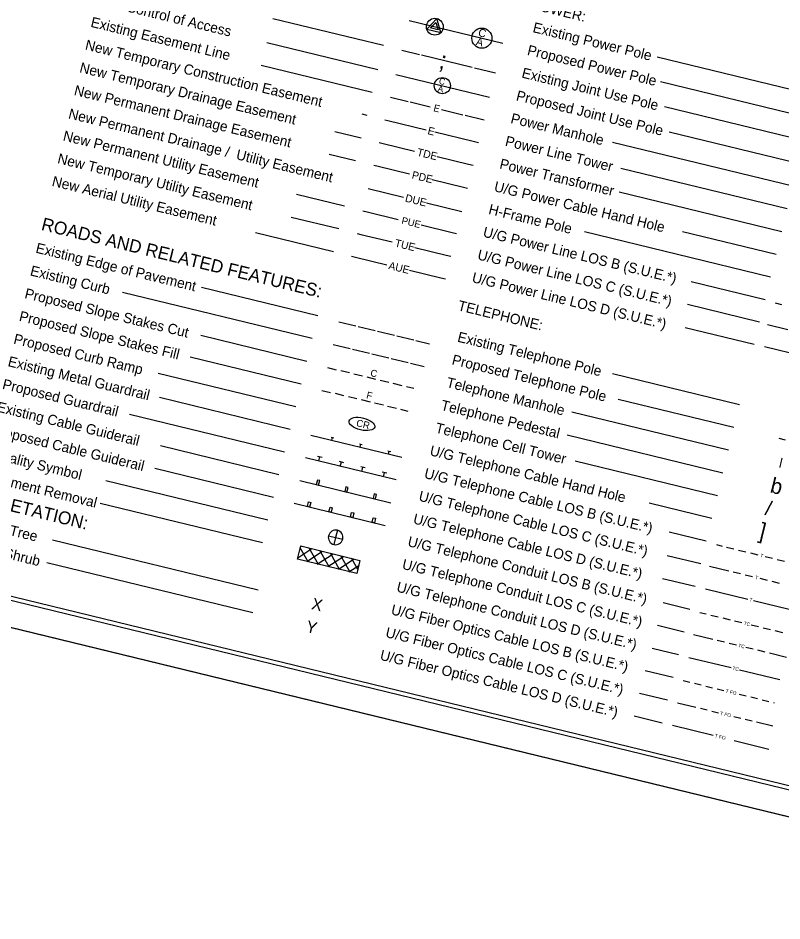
# Model space of a CAD drawing. Extents: x 1532568 to 1534465, y 472683 to 474150.
# Drawn here: x 1533179 to 1533832, y 472683 to 473455 of the extents above; entities that cross this region are included whole.
import ezdxf

# ---------------------------------------------------------------- set-up
doc = ezdxf.new("R2010")
doc.units = 0
for name, color, linetype in [('Prop Easement Permanent Drainage Utility', 7, 'Continuous'), ('Prop WCC CELL', 7, 'Continuous'), ('Sheet Cutting Line CELL', 7, 'Continuous'), ('Sheet Plot Border Inside CELL', 7, 'Continuous'), ('Sheet Plot Border Outside CELL', 7, 'Continuous'), ('Sheet Symbology CELL', 7, 'Continuous')]:
    doc.layers.add(name, color=color, linetype=linetype)

msp = doc.modelspace()

# ---------------------------------------------------------------- linework, layer by layer
at = {"layer": 'Prop Easement Permanent Drainage Utility'}
for p, q in [((1533478.48, 473309.25), (1533508.89, 473301.85)), ((1533528.32, 473297.12), (1533558.64, 473289.74))]:
    msp.add_line(p, q, dxfattribs=at)
at = {"layer": 'Prop WCC CELL'}
msp.add_ellipse((1533473.2, 473108.01), major_axis=(10.9, -2.65), ratio=0.462467, dxfattribs=at)
at = {"layer": 'Sheet Cutting Line CELL'}
msp.add_line((1532568.24, 473081.26), (1534204.47, 472683), dxfattribs=at)
at = {"layer": 'Sheet Plot Border Inside CELL'}
msp.add_lwpolyline([(1532586.18, 473100), (1534205.41, 472705.88), (1534454.94, 473731.04), (1532835.71, 474125.17)], close=True, dxfattribs=at)
at = {"layer": 'Sheet Plot Border Outside CELL'}
msp.add_lwpolyline([(1532568.24, 473081.26), (1534204.47, 472683), (1534464.62, 473751.79), (1532828.39, 474150.06)], close=True, dxfattribs=at)
at = {"layer": 'Sheet Symbology CELL'}
for p, q in [((1533491.74, 473431.51), (1533396.96, 473454.58)), ((1533513.48, 473453.06), (1533593.64, 473433.55)), ((1533535.54, 473447.69), (1533535.54, 473447.69)), ((1533486.69, 473410.77), (1533391.91, 473433.84)), ((1533507.31, 473427.72), (1533522.34, 473424.06)), ((1533524.28, 473423.59), (1533567.43, 473413.09)), ((1533860.48, 473389), (1533725.71, 473421.8)), ((1533481.96, 473391.33), (1533387.18, 473414.4)), ((1533502.27, 473406.97), (1533582.42, 473387.46)), ((1533569.38, 473412.61), (1533587.47, 473408.21)), ((1533855.75, 473369.57), (1533728.55, 473400.53)), ((1533497.54, 473387.54), (1533512.61, 473383.87)), ((1533514.55, 473383.4), (1533531.55, 473379.26)), ((1533541.27, 473376.9), (1533559.49, 473372.46)), ((1533851.02, 473350.14), (1533731.98, 473379.11)), ((1533477.6, 473371.81), (1533473.55, 473372.8)), ((1533492.81, 473368.11), (1533495.34, 473367.49)), ((1533495.34, 473367.49), (1533528.14, 473359.51)), ((1533561.43, 473371.99), (1533577.69, 473368.03)), ((1533472.5, 473352.47), (1533450.01, 473357.94)), ((1533535.42, 473357.74), (1533568.22, 473349.75)), ((1533846.29, 473330.7), (1533736, 473357.55)), ((1533488.08, 473348.68), (1533491.33, 473347.88)), ((1533491.33, 473347.88), (1533518.05, 473341.38)), ((1533568.22, 473349.75), (1533572.96, 473348.6)), ((1533841.56, 473311.27), (1533687.56, 473348.76)), ((1533467.77, 473333.04), (1533445.28, 473338.51)), ((1533537.48, 473336.65), (1533564.2, 473330.15)), ((1533483.35, 473329.24), (1533487.04, 473328.35)), ((1533487.04, 473328.35), (1533513.76, 473321.84)), ((1533564.2, 473330.15), (1533568.23, 473329.17)), ((1533836.83, 473291.84), (1533694.48, 473326.49)), ((1533533.19, 473317.11), (1533559.91, 473310.61)), ((1533559.91, 473310.61), (1533563.5, 473309.73)), ((1533832.1, 473272.41), (1533693.25, 473306.2)), ((1533458.31, 473294.16), (1533417.37, 473304.13)), ((1533473.88, 473290.37), (1533477.61, 473289.46)), ((1533477.61, 473289.46), (1533504.33, 473282.96)), ((1533453.58, 473274.73), (1533412.64, 473284.69)), ((1533523.76, 473278.23), (1533550.48, 473271.73)), ((1533448.85, 473255.3), (1533382.33, 473271.49)), ((1533469.15, 473270.94), (1533472.41, 473270.15)), ((1533472.41, 473270.15), (1533499.13, 473263.64)), ((1533550.48, 473271.73), (1533554.04, 473270.86)), ((1533822.64, 473233.54), (1533663.39, 473272.3)), ((1533827.37, 473252.97), (1533747.38, 473272.44)), ((1533518.56, 473258.91), (1533545.28, 473252.41)), ((1533464.42, 473251.51), (1533467.68, 473250.71)), ((1533467.68, 473250.71), (1533494.4, 473244.21)), ((1533545.28, 473252.41), (1533549.31, 473251.43)), ((1533513.83, 473239.48), (1533540.55, 473232.98)), ((1533540.55, 473232.98), (1533544.58, 473231.99)), ((1533817.91, 473214.11), (1533754.83, 473229.46)), ((1533430.76, 473180.98), (1533268.35, 473220.51)), ((1533435.49, 473200.41), (1533336.04, 473224.62)), ((1533813.27, 473195.05), (1533751.69, 473210.04)), ((1533826.55, 473211.5), (1533831.89, 473210.2)), ((1533453.36, 473195.47), (1533467.93, 473191.92)), ((1533469.88, 473191.45), (1533484.45, 473187.9)), ((1533808.63, 473175.99), (1533749.66, 473190.34)), ((1533819.97, 473193.02), (1533837.48, 473188.76)), ((1533426.03, 473161.55), (1533335.49, 473183.59)), ((1533486.39, 473187.43), (1533500.97, 473183.88)), ((1533502.91, 473183.41), (1533517.49, 473179.86)), ((1533448.63, 473176.04), (1533463.2, 473172.49)), ((1533519.43, 473179.39), (1533531.09, 473176.55)), ((1533817.45, 473174.12), (1533854.46, 473165.12)), ((1533465.15, 473172.02), (1533479.72, 473168.47)), ((1533481.66, 473168), (1533496.24, 473164.45)), ((1533421.3, 473142.11), (1533326.33, 473165.23)), ((1533498.18, 473163.98), (1533512.76, 473160.43)), ((1533514.7, 473159.96), (1533526.36, 473157.12)), ((1533416.57, 473122.68), (1533299.07, 473151.28)), ((1533443.79, 473156.14), (1533451.17, 473154.35)), ((1533462.54, 473151.58), (1533455.2, 473153.37)), ((1533473.71, 473148.86), (1533466.33, 473150.66)), ((1533796.05, 473124.32), (1533687.34, 473150.78)), ((1533485.13, 473146.08), (1533477.55, 473147.93)), ((1533496.25, 473143.37), (1533488.72, 473145.21)), ((1533507.48, 473140.64), (1533499.85, 473142.5)), ((1533439.06, 473136.71), (1533446.44, 473134.91)), ((1533517.48, 473138.21), (1533511.26, 473139.72)), ((1533411.72, 473103.4), (1533300.14, 473130.56)), ((1533457.81, 473132.15), (1533450.47, 473133.93)), ((1533468.98, 473129.43), (1533461.6, 473131.23)), ((1533480.4, 473126.65), (1533472.82, 473128.49)), ((1533791.32, 473104.88), (1533692.16, 473129.02)), ((1533491.52, 473123.94), (1533483.99, 473125.77)), ((1533502.75, 473121.21), (1533495.12, 473123.07)), ((1533512.75, 473118.77), (1533506.53, 473120.29)), ((1533406.99, 473083.97), (1533274.61, 473116.19)), ((1533786.59, 473085.45), (1533652.64, 473118.06)), ((1533429.58, 473098.46), (1533507.31, 473079.54)), ((1533446.83, 473096.84), (1533449.26, 473096.25)), ((1533447.45, 473094.11), (1533448.04, 473096.54)), ((1533781.86, 473066.02), (1533648.59, 473098.46)), ((1533402.26, 473064.54), (1533300.91, 473089.2)), ((1533471.12, 473090.93), (1533473.55, 473090.33)), ((1533471.74, 473088.2), (1533472.33, 473090.63)), ((1533835.34, 473094.16), (1533829.87, 473095.49)), ((1533495.41, 473085.01), (1533497.84, 473084.42)), ((1533496.03, 473082.29), (1533496.62, 473084.72)), ((1533502.58, 473060.11), (1533424.85, 473079.03)), ((1533435.24, 473080.57), (1533439.12, 473079.62)), ((1533436.25, 473076.26), (1533437.18, 473080.09)), ((1533453.7, 473076.07), (1533457.58, 473075.13)), ((1533454.71, 473071.76), (1533455.64, 473075.6)), ((1533777.13, 473046.59), (1533655.46, 473076.2)), ((1533397.53, 473045.11), (1533296.18, 473069.77)), ((1533472.16, 473071.58), (1533476.05, 473070.63)), ((1533473.17, 473067.27), (1533474.1, 473071.11)), ((1533490.62, 473067.09), (1533494.51, 473066.14)), ((1533491.63, 473062.78), (1533492.56, 473066.61)), ((1533392.8, 473025.67), (1533254.22, 473059.4)), ((1533420.12, 473059.6), (1533497.85, 473040.68)), ((1533388.07, 473006.24), (1533249.49, 473039.97)), ((1533415.39, 473040.16), (1533493.12, 473021.24)), ((1533772.4, 473027.15), (1533718.93, 473040.17)), ((1533444.64, 473012.45), (1533450.72, 473010.97)), ((1533452.19, 473017.04), (1533450.72, 473010.97)), ((1533767.67, 473007.72), (1533735.82, 473015.47)), ((1533384.55, 472965.86), (1533208.57, 473008.69)), ((1533418.11, 472992.33), (1533420.87, 473003.7)), ((1533420.73, 473003.11), (1533421.41, 473003.57)), ((1533420.87, 473003.7), (1533471.5, 472991.37)), ((1533450.72, 473010.97), (1533449.24, 473004.9)), ((1533450.72, 473010.97), (1533456.79, 473009.49)), ((1533776.24, 473004.81), (1533781.12, 473003.63)), ((1533418.38, 472993.45), (1533430.45, 473001.37)), ((1533427.1, 472990.14), (1533420.45, 473001.95)), ((1533426.03, 472990.4), (1533439.48, 472999.17)), ((1533436.13, 472987.94), (1533428.21, 473001.91)), ((1533435.01, 472988.21), (1533448.52, 472996.97)), ((1533445.12, 472985.75), (1533437.25, 472999.71)), ((1533454.15, 472983.55), (1533446.23, 472997.52)), ((1533785.01, 473002.68), (1533791.33, 473001.14)), ((1533795.21, 473000.2), (1533801.53, 472998.66)), ((1533805.41, 472997.71), (1533811.73, 472996.18)), ((1533379.82, 472946.42), (1533203.84, 472989.26)), ((1533468.73, 472980.01), (1533418.11, 472992.33)), ((1533444.05, 472986.01), (1533457.51, 472994.78)), ((1533453.09, 472983.81), (1533466.49, 472992.59)), ((1533463.19, 472981.35), (1533455.22, 472995.34)), ((1533469.62, 472983.65), (1533464.26, 472993.14)), ((1533471.5, 472991.37), (1533468.73, 472980.01)), ((1533762.94, 472988.29), (1533734.16, 472995.3)), ((1533817.95, 472994.66), (1533824.26, 472993.13)), ((1533828.15, 472992.18), (1533834.47, 472990.64)), ((1533462.07, 472981.63), (1533470.46, 472987.1)), ((1533770.48, 472986.45), (1533786.79, 472982.49)), ((1533790.67, 472981.54), (1533796.99, 472980)), ((1533758.21, 472968.86), (1533730.18, 472975.68)), ((1533800.87, 472979.06), (1533807.19, 472977.52)), ((1533813.41, 472976.01), (1533819.72, 472974.47)), ((1533823.61, 472973.52), (1533829.93, 472971.99)), ((1533767.05, 472967.07), (1533803.13, 472958.29)), ((1533753.48, 472949.42), (1533730.69, 472954.97)), ((1533807.98, 472957.1), (1533849.16, 472947.08)), ((1533762.14, 472946.88), (1533767.57, 472945.56)), ((1533771.45, 472944.61), (1533777.77, 472943.07)), ((1533781.66, 472942.13), (1533787.97, 472940.59)), ((1533748.75, 472929.99), (1533725.96, 472935.54)), ((1533791.86, 472939.64), (1533798.17, 472938.11)), ((1533805.95, 472936.21), (1533812.26, 472934.68)), ((1533756.59, 472928.08), (1533773.14, 472924.06)), ((1533816.15, 472933.73), (1533822.47, 472932.19)), ((1533826.35, 472931.25), (1533832.67, 472929.71)), ((1533777.03, 472923.11), (1533783.34, 472921.57)), ((1533787.23, 472920.63), (1533793.55, 472919.09)), ((1533744.02, 472910.56), (1533721.23, 472916.11)), ((1533801.32, 472917.2), (1533807.63, 472915.66)), ((1533811.52, 472914.71), (1533817.84, 472913.18)), ((1533821.72, 472912.23), (1533836.17, 472908.71)), ((1533752.77, 472908.38), (1533788.8, 472899.61)), ((1533739.29, 472891.13), (1533715.37, 472896.95)), ((1533796.09, 472897.84), (1533830.5, 472889.46)), ((1533747.95, 472888.57), (1533753.62, 472887.19)), ((1533757.51, 472886.24), (1533763.34, 472884.83)), ((1533767.22, 472883.88), (1533773.05, 472882.46)), ((1533776.94, 472881.51), (1533782.77, 472880.1)), ((1533734.56, 472871.69), (1533710.64, 472877.52)), ((1533795.89, 472876.9), (1533801.72, 472875.48)), ((1533805.6, 472874.54), (1533811.43, 472873.12)), ((1533743.14, 472869.6), (1533758.71, 472865.82)), ((1533762.6, 472864.87), (1533768.43, 472863.45)), ((1533815.32, 472872.17), (1533821.15, 472870.75)), ((1533825.03, 472869.81), (1533825.68, 472869.65)), ((1533729.83, 472852.26), (1533705.91, 472858.08)), ((1533772.31, 472862.51), (1533778.14, 472861.09)), ((1533791.26, 472857.89), (1533797.09, 472856.47)), ((1533738.67, 472850.45), (1533773.53, 472841.96)), ((1533800.97, 472855.53), (1533806.8, 472854.11)), ((1533810.69, 472853.16), (1533824.6, 472849.78)), ((1533791.41, 472837.22), (1533821.17, 472829.97))]:
    msp.add_line(p, q, dxfattribs=at)
for points in [[(1534442.19, 473731.52), (1532984.74, 474086.27), (1532736.66, 473067.05), (1534194.1, 472712.3)], [(1533528.61, 473445.67), (1533540.76, 473442.72), (1533537.24, 473454.69)], [(1533531.92, 473446.64), (1533536.43, 473451.35), (1533538.27, 473445.09)], [(1533434.19, 473056.17), (1533436.13, 473055.7), (1533437.08, 473059.59), (1533435.13, 473060.06)], [(1533458.48, 473050.26), (1533460.42, 473049.79), (1533461.37, 473053.67), (1533459.42, 473054.15)], [(1533482.77, 473044.35), (1533484.71, 473043.88), (1533485.66, 473047.76), (1533483.72, 473048.24)], [(1533427.48, 473041.34), (1533429.42, 473040.87), (1533428.47, 473036.98), (1533426.53, 473037.45)], [(1533445.94, 473036.85), (1533447.88, 473036.37), (1533446.94, 473032.49), (1533444.99, 473032.96)], [(1533464.4, 473032.35), (1533466.34, 473031.88), (1533465.4, 473027.99), (1533463.45, 473028.47)], [(1533482.86, 473027.86), (1533484.8, 473027.39), (1533483.86, 473023.5), (1533481.91, 473023.97)]]:
    msp.add_lwpolyline(points, close=True, dxfattribs=at)
for centre, radius in [((1533535.54, 473447.69), 7.2), ((1533575.76, 473437.9), 8.61), ((1533541.98, 473397.31), 6.89)]:
    msp.add_circle(centre, radius, dxfattribs=at)
for start, end in [(166.31436, 256.3189), (76.31436, 166.3189), (346.31436, 76.3189), (256.31436, 346.3189)]:
    msp.add_arc((1533450.72, 473010.97), 6.25, start, end, dxfattribs=at)

# ---------------------------------------------------------------- texts
at = {"layer": 'Prop Easement Permanent Drainage Utility'}
msp.add_text('DUE', height=6.55, rotation=346.31998, dxfattribs=at).set_placement((1533509.66, 473298.26))
at = {"layer": 'Prop WCC CELL'}
msp.add_text('CR', height=6, rotation=346.31998, dxfattribs=at).set_placement((1533467.92, 473106.25))
at = {"layer": 'Sheet Symbology CELL'}
for s, height, p in [('New Control of Access', 8.75, (1533245.43, 473467.16)), ('POWER:', 8.75, (1533617.32, 473463.07)), ('Existing Easement Line', 8.75, (1533240.7, 473447.73)), ('Existing Power Pole', 8.75, (1533618.7, 473443.18)), ('C', 6.75, (1533572.15, 473439.82)), ('New Temporary Construction Easement', 8.75, (1533235.97, 473428.3)), ('A', 6.75, (1533570.21, 473432.11)), ('Proposed Power Pole', 8.75, (1533613.97, 473423.75)), (';', 15, (1533538.33, 473412.45)), ('New Temporary Drainage Easement', 8.75, (1533231.24, 473408.86)), ('Existing Joint Use Pole', 8.75, (1533609.24, 473404.33)), ('New Permanent Drainage Easement', 8.75, (1533226.51, 473389.43)), ('A', 5.4, (1533537.6, 473392.53)), ('C', 5.4, (1533538.61, 473398.96)), ('Proposed Joint Use Pole', 8.75, (1533604.52, 473384.88)), ('New Permanent Drainage /  Utility Easement', 8.75, (1533221.65, 473369.43)), ('E', 6, (1533533.95, 473375.59)), ('Power Manhole', 8.75, (1533599.79, 473365.45)), ('New Permanent Utility Easement', 8.75, (1533217.05, 473350.56)), ('E', 6.55, (1533528.91, 473355.93)), ('Power Line Tower', 8.75, (1533595.06, 473346.03)), ('TDE', 6.55, (1533519.8, 473337.56)), ('New Temporary Utility Easement', 8.75, (1533212.32, 473331.12)), ('Power Transformer', 8.75, (1533590.32, 473326.6)), ('PDE', 6.55, (1533515.41, 473318.04)), ('New Aerial Utility Easement', 8.75, (1533207.59, 473311.69)), ('U/G Power Cable Hand Hole', 8.75, (1533585.61, 473307.15)), ('H-Frame Pole', 8.75, (1533580.88, 473287.72)), ('ROADS AND RELATED FEATURES:', 11, (1533198.42, 473274.02)), ('PUE', 6, (1533506.63, 473279.31)), ('U/G Power Line LOS B (S.U.E.*)', 8.75, (1533576.15, 473268.28)), ('TUE', 6.55, (1533500.85, 473259.83)), ('Existing Edge of Pavement', 8.75, (1533193.69, 473254.58)), ('U/G Power Line LOS C (S.U.E.*)', 8.75, (1533571.44, 473248.83)), ('Existing Curb', 8.75, (1533188.96, 473235.15)), ('AUE', 6.55, (1533495.49, 473240.55)), ('U/G Power Line LOS D (S.U.E.*)', 8.75, (1533566.73, 473229.38)), ('Proposed Slope Stakes Cut', 8.75, (1533184.23, 473215.72)), ('TELEPHONE:', 8.75, (1533554.59, 473205.36)), ('Proposed Slope Stakes Fill', 8.75, (1533179.5, 473196.29)), ('Proposed Curb Ramp', 8.75, (1533174.77, 473176.85)), ('Existing Telephone Pole', 8.75, (1533554.3, 473178.49)), ('Existing Metal Guardrail', 8.75, (1533169.92, 473157.57)), ('Proposed Telephone Pole', 8.75, (1533549.57, 473159.06)), ('C', 5.93, (1533479.95, 473149.13)), ('Proposed Guardrail', 8.75, (1533165.2, 473138.15)), ('Telephone Manhole', 8.75, (1533544.84, 473139.63)), ('F', 5.93, (1533476.54, 473130.02)), ('Telephone Pedestal', 8.75, (1533540.11, 473120.19)), ('Existing Cable Guiderail', 8.75, (1533160.47, 473118.72)), ('Proposed Cable Guiderail', 8.75, (1533155.74, 473099.29)), ('Telephone Cell Tower', 8.75, (1533535.39, 473100.76)), ('U/G Telephone Cable Hand Hole', 8.75, (1533530.66, 473081.33)), ('Equality Symbol', 8.75, (1533151.01, 473079.85)), ('l', 8.25, (1533829.23, 473070.83)), ('Pavement Removal', 8.75, (1533146.28, 473060.42)), ('U/G Telephone Cable LOS B (S.U.E.*)', 8.75, (1533525.93, 473061.89)), ('b', 13.2, (1533821.51, 473049.58)), ('VEGETATION:', 11, (1533141.52, 473040.91)), ('U/G Telephone Cable LOS C (S.U.E.*)', 8.75, (1533521.2, 473042.46)), ('/', 12.5, (1533817.2, 473030.4)), ('Single Tree', 8.75, (1533136.53, 473021.57)), ('U/G Telephone Cable LOS D (S.U.E.*)', 8.75, (1533516.47, 473023.03)), (']', 13.5, (1533811.87, 473010.6)), ('U/G Telephone Conduit LOS B (S.U.E.*)', 8.75, (1533511.74, 473003.6)), ('Single Shrub', 8.75, (1533131.8, 473002.14)), ('T', 3, (1533813.56, 472994.19)), ('U/G Telephone Conduit LOS C (S.U.E.*)', 8.75, (1533507.01, 472984.16)), ('U/G Telephone Conduit LOS D (S.U.E.*)', 8.75, (1533502.28, 472964.73)), ('T', 3, (1533809.02, 472975.53)), ('X', 10, (1533429.42, 472949.79)), ('T', 3, (1533804.28, 472956.46)), ('U/G Fiber Optics Cable LOS B (S.U.E.*)', 8.75, (1533497.55, 472945.3)), ('Y', 10, (1533424.69, 472930.36)), ('U/G Fiber Optics Cable LOS C (S.U.E.*)', 8.75, (1533492.82, 472925.87)), ('TC', 3, (1533799.37, 472936.27)), ('TC', 3, (1533794.75, 472917.25)), ('U/G Fiber Optics Cable LOS D (S.U.E.*)', 8.75, (1533488.09, 472906.43)), ('TC', 3, (1533789.76, 472897.83)), ('T FO', 3, (1533783.87, 472878.28)), ('T FO', 3, (1533779.24, 472859.27)), ('T FO', 3, (1533774.63, 472840.15))]:
    msp.add_text(s, height=height, rotation=346.31998, dxfattribs=at).set_placement(p)

doc.saveas('drawing.dxf')
